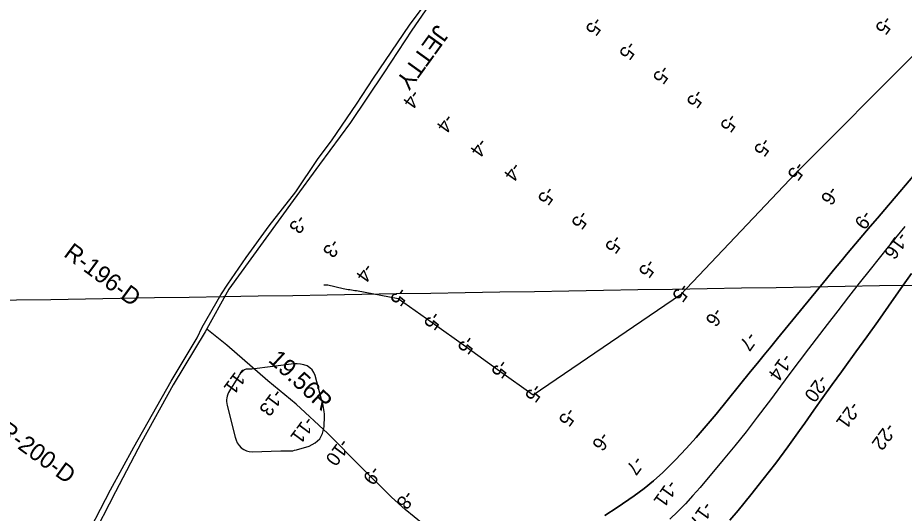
# Model space of a CAD drawing. Extents: x 3879599 to 3900814, y 146526 to 168888.
# Drawn here: x 3889001 to 3891140, y 156064 to 157260 of the extents above; entities that cross this region are included whole.
import ezdxf

# ---------------------------------------------------------------- set-up
doc = ezdxf.new("R2010")
doc.units = 0
for name, color, linetype in [('V-GRID-MAJR', 7, 'Continuous'), ('V-LEVE-TOET', 7, 'Continuous'), ('V-RIVR-JETY', 7, 'Continuous'), ('V-RIVR-RANG', 7, 'Continuous'), ('V-RIVR-RANG-IDEN', 7, 'Continuous'), ('V-STRM-FMON', 7, 'Continuous'), ('V-TOPO-DPTH', 7, 'Continuous'), ('V-TOPO-MINR', 7, 'Continuous')]:
    doc.layers.add(name, color=color, linetype=linetype)

msp = doc.modelspace()

# ---------------------------------------------------------------- linework, layer by layer
at = {"layer": 'V-GRID-MAJR'}
msp.add_spline([(3884717.1, 156508.2), (3888748.3, 156574.8), (3894080.4, 156663.6), (3896663.2, 156706.9)], degree=3, dxfattribs=at)
at = {"layer": 'V-LEVE-TOET'}
msp.add_lwpolyline([(3890403.6, 155730.2), (3890324.9, 155789.6), (3890228.5, 155859.5), (3890140.2, 155921.2), (3890023.2, 156001.7), (3889936.4, 156072.9), (3889903.3, 156102.9), (3889830, 156175.1), (3889749.8, 156256.5), (3889673, 156327.5), (3889604.8, 156383.4), (3889506.1, 156470.1), (3889457.7, 156508.3)], dxfattribs=at)
at = {"layer": 'V-RIVR-JETY'}
for points in [[(3890041.5, 157361.1), (3889952, 157230.2), (3889885, 157127), (3889804.4, 157007.3), (3889729.7, 156906.4), (3889665.7, 156818.9), (3889564.1, 156678.4), (3889510.3, 156604.6), (3889453.5, 156501.9), (3889376.4, 156373.6), (3889299.8, 156235.8), (3889237.6, 156115.6), (3889176.7, 155998.2), (3889122.2, 155901.8), (3889067.7, 155804.7), (3889024.5, 155726.9), (3888970.4, 155628.7)], [(3888957.2, 155625.1), (3889001.4, 155707.5), (3889043, 155781.1), (3889093.3, 155875), (3889153.3, 155982.3), (3889225.3, 156120), (3889281.1, 156223.4), (3889371.8, 156382.6), (3889434.5, 156487.4), (3889446.7, 156513), (3889491, 156591.5), (3889508.1, 156616.8), (3889552.9, 156681.4), (3889608.3, 156758), (3889672.4, 156840.3), (3889725, 156918.2), (3889760.3, 156965.6), (3889818.4, 157051.6), (3889860.1, 157114.1), (3889946.9, 157242.3), (3890015.4, 157336.1)]]:
    msp.add_lwpolyline(points, dxfattribs=at)
at = {"layer": 'V-TOPO-DPTH'}
for points in [[(3890418.2, 156058.5), (3890447.7, 156077.6), (3890488.7, 156106.1), (3890512.5, 156123.8), (3890535.7, 156142.3), (3890557.6, 156162.1), (3890578.9, 156182.8), (3890588.7, 156193), (3890613.9, 156219.8), (3890638.7, 156246.9), (3890662.7, 156274.8), (3890686.2, 156303), (3890769.8, 156406.2), (3890786, 156426.1), (3890802.2, 156446), (3890818.3, 156465.8), (3890834.6, 156485.7), (3890952.5, 156629.8), (3890969.9, 156651), (3890987.4, 156672.1), (3891004.9, 156693.1), (3891022.5, 156714.1), (3891040.1, 156735), (3891057.8, 156755.9), (3891075.5, 156776.8), (3891093.3, 156797.6), (3891179.4, 156898.7)], [(3891157.6, 156642.5), (3891138.2, 156614.7), (3891102.4, 156563.9), (3891076.3, 156527), (3891050.1, 156490.2), (3891023.7, 156453.5), (3890997.2, 156416.8), (3890988.9, 156405.4), (3890966.5, 156374.5), (3890944.3, 156343.5), (3890922.2, 156312.4), (3890900.2, 156281.3), (3890887.8, 156263.8), (3890859.3, 156224.1), (3890830.3, 156184.9), (3890800.4, 156146.2), (3890770, 156108), (3890739.4, 156070.2), (3890719.9, 156047)], [(3890719.9, 156047), (3890739.4, 156070.2), (3890770, 156108), (3890800.4, 156146.2), (3890830.3, 156184.9), (3890859.3, 156224.1), (3890887.8, 156263.8), (3890900.2, 156281.3), (3890922.2, 156312.4), (3890944.3, 156343.5), (3890966.5, 156374.5), (3890988.9, 156405.4), (3890997.2, 156416.8), (3891023.7, 156453.5), (3891050.1, 156490.2), (3891076.3, 156527), (3891102.4, 156563.9), (3891138.2, 156614.7), (3891157.6, 156642.5)], [(3889550.5, 156411), (3889548.2, 156409.9), (3889546.1, 156408.5), (3889544.4, 156407.1), (3889541.7, 156404.6), (3889539.1, 156401.9), (3889536.8, 156398.9), (3889534.7, 156395.8), (3889512.2, 156359.5), (3889510, 156355.4), (3889508.2, 156351.2), (3889506.8, 156346.9), (3889505.8, 156342.4), (3889505.3, 156337.8), (3889505.1, 156333.3), (3889505.6, 156328.7), (3889506.4, 156324.2), (3889525.6, 156247.2), (3889528, 156240.2), (3889531.2, 156233.6), (3889535.6, 156227.7), (3889540.7, 156222.2), (3889546.7, 156218), (3889553.1, 156214.8), (3889560, 156213.1), (3889567.3, 156212.4), (3889636.5, 156214.3), (3889641.3, 156214.4), (3889646, 156214.5), (3889650.7, 156214.5), (3889655.5, 156214.4), (3889660.2, 156214.5), (3889664.8, 156214.9), (3889669.5, 156215.8), (3889674, 156216.9), (3889704.9, 156225.9), (3889719.2, 156233.5), (3889730.4, 156243.4), (3889737.1, 156256.8), (3889740.8, 156272.6), (3889741.4, 156299), (3889741.3, 156304), (3889741, 156309), (3889740.2, 156314), (3889739.2, 156319), (3889738, 156323.9), (3889736.8, 156328.8), (3889735.5, 156333.7), (3889734.2, 156338.6), (3889719, 156396.4), (3889716, 156403.7), (3889711.8, 156410.2), (3889706.1, 156415.3), (3889699.4, 156419.5), (3889691.6, 156422.3), (3889683.6, 156424.1), (3889675.5, 156424.7), (3889667.2, 156424.4), (3889566.2, 156412.1), (3889563.5, 156411.9), (3889560.8, 156411.7), (3889558.2, 156411.7), (3889555.5, 156411.7), (3889552.9, 156411.5), (3889550.5, 156411)]]:
    msp.add_lwpolyline(points, dxfattribs=at)
at = {"layer": 'V-TOPO-MINR'}
for points in [[(3891171.1, 157178.4), (3890878.5, 156884.7), (3890600.3, 156591.5), (3890245, 156349.1), (3890163.7, 156407.2), (3890082.3, 156465.4), (3890001, 156523.5), (3889919.6, 156581.6), (3889818.9, 156600.6), (3889814.9, 156601.3), (3889810.9, 156601.9), (3889806.9, 156602.5), (3889802.9, 156603.1), (3889798.9, 156603.6), (3889794.9, 156604.3), (3889790.9, 156605), (3889786.9, 156605.8), (3889749.3, 156614.3), (3889740.1, 156615)], [(3891179.4, 156898.7), (3891093.3, 156797.6), (3891075.5, 156776.8), (3891057.8, 156755.9), (3891040.1, 156735), (3891022.5, 156714.1), (3891004.9, 156693.1), (3890987.4, 156672.1), (3890969.9, 156651), (3890952.5, 156629.8), (3890834.6, 156485.7), (3890818.3, 156465.8), (3890802.2, 156446), (3890786, 156426.1), (3890769.8, 156406.2), (3890686.2, 156303), (3890662.7, 156274.8), (3890638.7, 156246.9), (3890613.9, 156219.8), (3890588.7, 156193), (3890578.9, 156182.8), (3890557.6, 156162.1), (3890535.7, 156142.3), (3890512.5, 156123.8), (3890488.7, 156106.1), (3890447.7, 156077.6), (3890418.2, 156058.5)], [(3891141.9, 156756.3), (3891119.6, 156728.9), (3891115.2, 156723.5), (3891110.7, 156718), (3891106.3, 156712.5), (3891101.8, 156706.9), (3891058, 156652.3), (3891031.8, 156619.3), (3891005.8, 156586.2), (3890980, 156553), (3890954.4, 156519.6), (3890909.5, 156460.5), (3890886.9, 156430.8), (3890864.5, 156401), (3890842.2, 156371.1), (3890820, 156341.2), (3890812.1, 156330.6), (3890785.7, 156295.5), (3890758.9, 156260.8), (3890731.4, 156226.6), (3890703.5, 156192.7), (3890647.9, 156126.4), (3890630.4, 156106.4), (3890612.5, 156086.8), (3890593.8, 156068), (3890574.6, 156049.7)], [(3891157.6, 156642.5), (3891138.2, 156614.7), (3891102.4, 156563.9), (3891076.3, 156527), (3891050.1, 156490.2), (3891023.7, 156453.5), (3890997.2, 156416.8), (3890988.9, 156405.4), (3890966.5, 156374.5), (3890944.3, 156343.5), (3890922.2, 156312.4), (3890900.2, 156281.3), (3890887.8, 156263.8), (3890859.3, 156224.1), (3890830.3, 156184.9), (3890800.4, 156146.2), (3890770, 156108), (3890739.4, 156070.2), (3890719.9, 156047)], [(3889550.5, 156411), (3889548.2, 156409.9), (3889546.1, 156408.5), (3889544.4, 156407.1), (3889541.7, 156404.6), (3889539.1, 156401.9), (3889536.8, 156398.9), (3889534.7, 156395.8), (3889512.2, 156359.5), (3889510, 156355.4), (3889508.2, 156351.2), (3889506.8, 156346.9), (3889505.8, 156342.4), (3889505.3, 156337.8), (3889505.1, 156333.3), (3889505.6, 156328.7), (3889506.4, 156324.2), (3889525.6, 156247.2), (3889528, 156240.2), (3889531.2, 156233.6), (3889535.6, 156227.7), (3889540.7, 156222.2), (3889546.7, 156218), (3889553.1, 156214.8), (3889560, 156213.1), (3889567.3, 156212.4), (3889636.5, 156214.3), (3889641.3, 156214.4), (3889646, 156214.5), (3889650.7, 156214.5), (3889655.5, 156214.4), (3889660.2, 156214.5), (3889664.8, 156214.9), (3889669.5, 156215.8), (3889674, 156216.9), (3889704.9, 156225.9), (3889719.2, 156233.5), (3889730.4, 156243.4), (3889737.1, 156256.8), (3889740.8, 156272.6), (3889741.4, 156299), (3889741.3, 156304), (3889741, 156309), (3889740.2, 156314), (3889739.2, 156319), (3889738, 156323.9), (3889736.8, 156328.8), (3889735.5, 156333.7), (3889734.2, 156338.6), (3889719, 156396.4), (3889716, 156403.7), (3889711.8, 156410.2), (3889706.1, 156415.3), (3889699.4, 156419.5), (3889691.6, 156422.3), (3889683.6, 156424.1), (3889675.5, 156424.7), (3889667.2, 156424.4), (3889566.2, 156412.1), (3889563.5, 156411.9), (3889560.8, 156411.7), (3889558.2, 156411.7), (3889555.5, 156411.7), (3889552.9, 156411.5), (3889550.5, 156411)]]:
    msp.add_lwpolyline(points, dxfattribs=at)

# ---------------------------------------------------------------- texts
at = {"layer": 'V-RIVR-JETY'}
msp.add_text('JETTY', height=42, rotation=234.222, dxfattribs=at).set_placement((3890011.9, 157246.2))
at = {"layer": 'V-RIVR-RANG'}
for s, rotation, p in [('-5', 234.1883, (3890392.4, 157265)), ('-5', 233.7983, (3891091.8, 157267.7)), ('-5', 234.1883, (3890473.6, 157206.7)), ('-5', 234.1883, (3890554.8, 157148.4)), ('-4', 234.0683, (3889952.2, 157089.1)), ('-5', 234.1883, (3890636.1, 157090.1)), ('-4', 234.0683, (3890033.4, 157030.6)), ('-5', 234.1883, (3890717.3, 157031.7)), ('-4', 234.0683, (3890114.5, 156972.1)), ('-5', 234.1883, (3890798.5, 156973.4)), ('-4', 234.0683, (3890195.6, 156913.6)), ('-5', 234.1883, (3890879.8, 156915.1)), ('-5', 234.0683, (3890277.2, 156855.9)), ('-6', 234.1883, (3890960.5, 156856.2)), ('-5', 234.0683, (3890358.4, 156797.4)), ('-9', 234.1883, (3891041.7, 156797.7)), ('-3', 234.3083, (3889677.2, 156787.1)), ('-16', 234.1883, (3891127.5, 156745.7)), ('-3', 234.3083, (3889758.6, 156729)), ('-5', 234.0683, (3890439.5, 156738.9)), ('-4', 234.3083, (3889838.9, 156669.5)), ('-5', 234.0683, (3890520.6, 156680.4)), ('-5', 234.0683, (3890601.7, 156621.9)), ('-5', 234.3083, (3889920.8, 156612.1)), ('-5', 234.3083, (3890002.2, 156554)), ('-6', 234.0683, (3890682.3, 156562.8)), ('-5', 234.3083, (3890083.6, 156495.8)), ('-7', 234.0683, (3890763.5, 156504.3)), ('-14', 234.0683, (3890849, 156451.9)), ('-5', 234.3083, (3890164.9, 156437.7)), ('-11', 233.3283, (3889535.2, 156419.3)), ('-20', 234.0683, (3890935.4, 156400.7)), ('-13', 233.3283, (3889620.7, 156366.7)), ('-5', 234.3083, (3890246.3, 156379.5)), ('-5', 234.3083, (3890327.6, 156321.4)), ('-21', 234.0683, (3891012.1, 156336.3)), ('-11', 233.3283, (3889695.9, 156300.3)), ('-22', 234.0683, (3891098.1, 156284.5)), ('-6', 234.3083, (3890408.6, 156262.6)), ('-10', 233.3283, (3889780.7, 156246.7)), ('-7', 234.3083, (3890489.9, 156204.5)), ('-9', 233.3283, (3889856.2, 156180.6)), ('-11', 234.3083, (3890571.7, 156146.9)), ('-8', 233.3283, (3889936.8, 156121.4)), ('-17', 234.3083, (3890657.1, 156094.4))]:
    msp.add_text(s, height=33.5, rotation=rotation, dxfattribs=at).set_placement(p)
at = {"layer": 'V-RIVR-RANG-IDEN'}
for s, rotation, p in [('R-196-D', 323.4664, (3889109.9, 156685.9)), ('R-200-D', 324.0718, (3888951.6, 156256))]:
    msp.add_text(s, height=41.5, rotation=rotation, dxfattribs=at).set_placement(p)
at = {"layer": 'V-STRM-FMON'}
msp.add_text('19.56R', height=42, rotation=316.9895, dxfattribs=at).set_placement((3889603.9, 156431.6))

doc.saveas('drawing.dxf')
